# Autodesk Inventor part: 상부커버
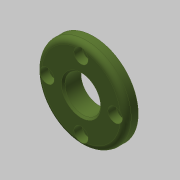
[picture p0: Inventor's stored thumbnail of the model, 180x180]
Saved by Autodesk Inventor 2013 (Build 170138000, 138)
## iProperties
Created: 2019-01
Part Number: 상부커버
Material: 알루미늄 6061
Document SubType Name: Modeling
Designer: mduedu
Density: 2.71 g/cm^3
Mass: 29.8168 g
Surface Area: 54.6428 cm^2
Volume: 11.0025 cm^3
Author: mduedu
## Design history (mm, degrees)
sketch "스케치1"
  geometry: L1 (0, 0)-(7, 0); L2 (7, 0)-(7, 25); L3 (7, 25)-(0, 25); L4 (0, 25)-(0, 0); L5 (7, 0)-(10, 0); L6 (10, 0)-(10, 14); L7 (10, 14)-(7, 14); L8 (7, 14)-(7, 0)
  constraints: 16 end point, 4 parallel, 2 horizontal, 2 perpendicular
  dimensions: "d0" = 50 diameter of L3 L1; "d2" = 10 distance between parallel lines of L6 L4; "d3" = 7 distance of L2.end L3.end; "d4" = 28 diameter of L7 L5
revolve "회전1" sketch "스케치1" stored, may be unused: angle "d5" = 90 deg
sketch "스케치2"
  geometry: C1 r 10 at (0, 0); 1 further point
  constraints: 1 centre point, 1 coincident
  dimensions: "d6" = 20 diameter of C1
extrude "돌출1" cut sketch "스케치2" stored distance "d7" = 10; taper "d8" = 0 deg
chamfer "모따기1" distance "d9" = 1; stored, may be unused: second distance "d10" = 2, angle "d11" = 45 deg
fillet "모깎기1" dims "d12" = 3
sketch "스케치3" dims "d13" = 38
  geometry: 6 further points
  constraints: 2 vertical alignment, 1 coincident, 7 other
  dimensions: "d16" = 360 deg dimension on point (0, 0) point (0, 19) (derived)
chamfer "모따기2" distance "d18" = 1; stored, may be unused: second distance "d19" = 2, angle "d20" = 45 deg
sketch "스케치4"
  geometry: 4 further points
  constraints: 4 other
hole "구멍1" sketch "스케치4" at (-19, 0), (0, -19), (19, 0), (0, 19) diameter "d21" = 4.5; stored, may be unused: countersink angle "d25" = 90 deg, drill point angle "d27" = 0 deg; dims "d22" = 6, "d23" = 8, "d24" = 4.6, "d26" = 8
node "솔리드1"
